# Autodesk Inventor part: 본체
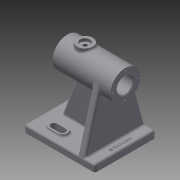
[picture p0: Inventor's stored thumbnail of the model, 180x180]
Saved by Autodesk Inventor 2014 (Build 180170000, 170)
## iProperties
Created: 2019-10
Part Number: 본체
Material: Aluminum 6061
Document SubType Name: Modeling
Designer: kh
Density: 2.71 g/cm^3
Appearance: Default
Mass: 588.435 g
Surface Area: 540.74 cm^2
Volume: 217.135 cm^3
Author: kh
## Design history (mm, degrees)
sketch "Sketch1"
  geometry: L1 (-50, -43)-(50, -43); L2 (50, -43)-(50, 43); L3 (50, 43)-(-50, 43); L4 (-50, 43)-(-50, -43); L5 (-50, -43)-(50, 43); L6 (50, -43)-(-50, 43); 1 further point
  constraints: 12 end point, 2 midpoint, 2 parallel, 1 horizontal, 1 perpendicular
  dimensions: "d0" = 100 distance of L3.end L2.end; "d1" = 86 distance of L1.end L2.end
extrude "Extrusion1" new body sketch "Sketch1" distance "d2" = 10; taper "d3" = 0 deg
sketch "Sketch2"
  geometry: L1 (-50, 0)-(50, 0) reference; L2 (-50, 0)-(-50, 86); L3 (-50, 86)-(32, 86); L4 (32, 86)-(32, 107); L5 (32, 107)-(-50, 107); L6 (-50, 107)-(-50, 86); L7 (32, 100.5)-(-30, 100.5); L8 (-30, 100.5)-(-30, 97.5); L9 (-30, 97.5)-(-50, 97.5); 1 further point
  constraints: 16 end point, 7 perpendicular, 2 point on line, 1 parallel
  dimensions: "d4" = 86 distance of L1.start L2.end; "d5" = 82 distance of L2.end L3.end; "d6" = 42 diameter of L5 L3; "d7" = 62 distance between parallel lines of L4 L8; "d8" = 23 diameter of L9 L3; "d9" = 29 diameter of L7 L3
revolve "Revolution1" sketch "Sketch2" stored, may be unused: angle "d10" = 90 deg
chamfer "Chamfer1" distance "d11" = 1; stored, may be unused: second distance "d12" = 2, angle "d13" = 45 deg
workplane "Work Plane1"
sketch "Sketch3"
  geometry: L1 (-32, 21)-(-32, -21) reference; L2 (-32, 0)-(-7, 0); C1 r 11 at (-7, 0); 1 further point
  constraints: 2 end point, 1 centre point, 1 coincident, 1 midpoint, 1 perpendicular
  dimensions: "d15" = 25 distance of L2.start L2.end; "d16" = 22 diameter of C1
extrude "Extrusion2" join sketch "Sketch3" stored distance "d17" = 10; taper "d18" = 0 deg
hole "Hole1" diameter "d21" = 5.242; stored, may be unused: countersink angle "d25" = 90 deg, drill point angle "d27" = 118 deg; dims "d22" = 6, "d23" = 14, "d24" = 4, "d26" = 8, "d85" = 10, "d86" = 10
workplane "Work Plane2"
sketch "Sketch5"
  geometry: L1 (-50, -43)-(50, -43) reference; L2 (50, -43)-(50, 43) reference; L3 (50, 43)-(-50, 43) reference; L4 (-50, 43)-(-50, -43) reference; L5 (50, 0)-(-50, 0); L6 (-24, 27)-(-12, 27); L7 (-24, 20)-(-12, 20); L8 (-12, 34)-(-24, 34); L9 (-24, 27)-(-12, 27); L10 (-24, 22.5)-(-12, 22.5); L11 (-12, 31.5)-(-24, 31.5); A1 r 7 centre (-24, 27) between (-24, 34) and (-24, 20); A2 r 7 centre (-12, 27) between (-12, 20) and (-12, 34); A3 r 4.5 centre (-24, 27) between (-24, 31.5) and (-24, 22.5); A4 r 4.5 centre (-12, 27) between (-12, 22.5) and (-12, 31.5); 3 further points
  constraints: 18 end point, 8 point on circle, 8 tangent, 4 centre point, 4 midpoint, 4 parallel, 1 coincident
  dimensions: "d31" = 14 diameter of A2; "d32" = 12 distance of L6.end L6.start; "d33" = 27 distance from line of L5 point (-18, 27); "d35" = 12 distance of L9.start L9.end; "d36" = 9 diameter of A4; "d84" = 26 horizontal distance of L3.end L9.start
  node "Projected Loop2"
extrude "Extrusion3" join sketch "Sketch5" stored distance "d37" = 10; taper "d38" = 0 deg
extrude "Extrusion4" cut sketch "Sketch5" stored distance "d39" = 10; taper "d40" = 0 deg
mirror "Mirror1"
workplane "Work Plane3"
fillet "Fillet1" dims "d44" = 3
fillet "Fillet2" dims "d45" = 3
sketch "Sketch7"
  geometry: L1 (-10, 3)-(-10, 83) reference; L2 (-7, 86)-(0, 86) reference; L3 (0, 86)-(0, 0) reference; L4 (0, 0)-(-7, 0) reference; L5 (-10, 3)-(-10, 83) reference; L6 (-7, 86)-(0, 86) reference; L7 (0, 86)-(0, 0) reference; L8 (0, 0)-(-7, 0) reference; L9 (-7.783, 0.104)-(-91.48, 22.728); L10 (-7.783, 85.896)-(-91.48, 63.272); L11 (-10, 3)-(-10, 83); C1 r 11.5 at (-86, 43) reference; C2 r 11.5 at (-86, 43) reference; A1 r 3 centre (-7, 83) between (-7, 86) and (-10, 83) reference; A2 r 3 centre (-7, 3) between (-10, 3) and (-7, 0) reference; A3 r 21 centre (-86, 43) between (-91.48, 22.728) and (-91.48, 63.272) reference; A4 r 3 centre (-7, 83) between (-7, 86) and (-10, 83) reference; A5 r 3 centre (-7, 3) between (-10, 3) and (-7, 0) reference; A6 r 21 centre (-86, 43) between (-91.48, 22.728) and (-91.48, 63.272) reference; A7 r 3 centre (-7, 3) between (-10, 3) and (-7.783, 0.104); A8 r 3 centre (-7, 83) between (-7.783, 85.896) and (-10, 83); A9 r 21 centre (-86, 43) between (-91.48, 22.728) and (-91.48, 63.272); 1 further point
  constraints: 14 point on circle, 10 tangent, 6 end point, 3 centre point, 3 coincident, 1 collinear
extrude "Extrusion6" join sketch "Sketch7" distance "d46" = 10; taper "d47" = 0 deg
sketch "Sketch8"
  geometry: L1 (47, 10)-(-25, 10) reference; L2 (50, 0)-(50, 7) reference; L3 (35, 10)-(22.683, 43.842); 1 further point
  constraints: 2 end point, 1 point on line
  dimensions: "d48" = 15 horizontal distance of L3.start L2.end; "d49" = 70 deg angle of L3 L1
feature "Rib1" sketch "Sketch8" dims "d50" = 1, "d51" = 10, "d52" = 0, "d53" = 0, "d54" = 1, "d55" = 1
fillet "Fillet3" dims "d56" = 3
fillet "Fillet4" dims "d57" = 3
sketch "Sketch9"
  geometry: L1 (37.641, -24.675)-(37.641, 24.675); L2 (37.641, 24.675)-(48.359, 24.675); L3 (48.359, 24.675)-(48.359, -24.675); L4 (48.359, -24.675)-(37.641, -24.675); L5 (37.641, -24.675)-(48.359, 24.675); L6 (37.641, 24.675)-(48.359, -24.675); L7 (-47, -43)-(47, -43) reference; L8 (50, -40)-(50, 40) reference; 2 further points
  constraints: 4 end point, 1 midpoint, 2 other
  dimensions: "d58" = 43 distance from line of point (43, 0) L7; "d59" = 7 distance from line of point (43, 0) L8
emboss "Emboss1" sketch "Sketch9" dims "d0" = 100, "d1" = 86, "d60" = 0.5, "d61" = 0
sketch "Sketch10"
  geometry: L1 (0, 0)-(-18, 0); C1 r 21 at (0, 0) reference; 2 further points
  constraints: 2 end point, 1 coincident, 1 horizontal
  dimensions: "d62" = 18 distance of L1.start L1.end
hole "Hole2" sketch "Sketch10" at (-18, 0) diameter "d63" = 2.621; stored, may be unused: countersink angle "d67" = 90 deg, drill point angle "d69" = 118 deg; dims "d64" = 8, "d65" = 14, "d66" = 4, "d68" = 10
pattern_circular "Circular Pattern1" dims angle "d71" = 360 deg
sketch "Sketch11"
  geometry: L1 (0, 0)-(18, 0); C1 r 21 at (0, 0) reference; 2 further points
  constraints: 2 end point, 1 coincident, 1 horizontal
  dimensions: "d73" = 18 distance of L1.start L1.end
hole "Hole3" sketch "Sketch11" at (18, 0) diameter "d74" = 2.621; stored, may be unused: countersink angle "d78" = 90 deg, drill point angle "d80" = 118 deg; dims "d75" = 8, "d76" = 14, "d77" = 4, "d79" = 10
pattern_circular "Circular Pattern2" dims angle "d82" = 360 deg
body "Solid1"
node "Project Cut Edges1"
node "Project Cut Edges2"
other parameters: "d30" = -13, "d41" = -15
